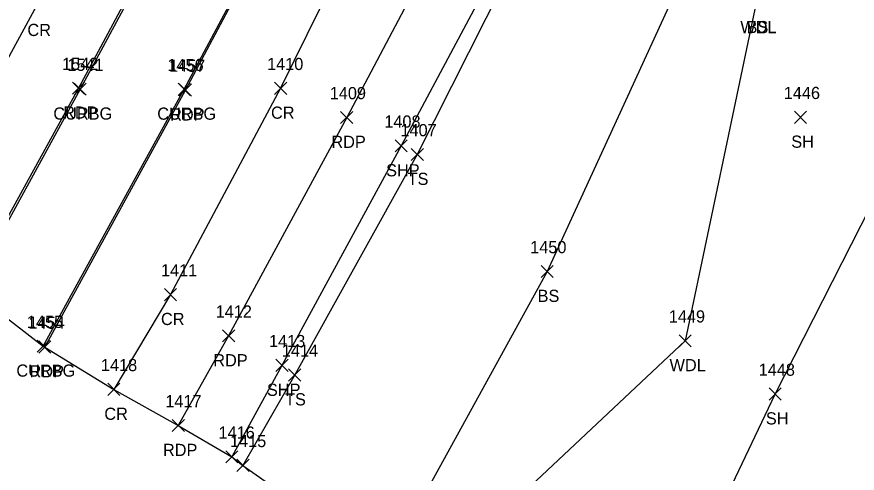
# Model space of a CAD drawing. Extents: x 1623612 to 1625808, y 621345 to 627748.
# Drawn here: x 1624455.5 to 1624593.5, y 625672.8 to 625747.8 of the extents above; entities that cross this region are included whole.
import ezdxf

# ---------------------------------------------------------------- set-up
doc = ezdxf.new("R2010")
doc.units = 0
for name, color, linetype in [('L_A', 7, 'Continuous'), ('L_I', 7, 'Continuous'), ('L_TIC', 7, 'Continuous'), ('LAWA', 7, 'Continuous'), ('LELB', 7, 'Continuous'), ('LSOGP', 7, 'Continuous'), ('P_A', 7, 'Continuous'), ('P_I', 7, 'Continuous'), ('P_TIC', 7, 'Continuous'), ('PET', 7, 'Continuous'), ('PRC', 7, 'Continuous'), ('PSP', 7, 'Continuous'), ('R_A', 7, 'Continuous'), ('R_I', 7, 'Continuous'), ('R_TIC', 7, 'Continuous'), ('RC', 7, 'Continuous')]:
    doc.layers.add(name, color=color, linetype=linetype)

msp = doc.modelspace()

# ---------------------------------------------------------------- linework, layer by layer
at = {"layer": 'L_TIC'}
for points in [[(1624583.14, 625730.27), (1624585.14, 625732.27)], [(1624585.14, 625730.27), (1624583.14, 625732.27)], [(1624520.23, 625724.16), (1624522.23, 625726.16)], [(1624522.23, 625724.16), (1624520.23, 625726.16)], [(1624541.54, 625704.94), (1624543.54, 625706.94)], [(1624543.54, 625704.94), (1624541.54, 625706.94)], [(1624564.22, 625693.56), (1624566.22, 625695.56)], [(1624566.22, 625693.56), (1624564.22, 625695.56)], [(1624500.1, 625687.94), (1624502.1, 625689.94)], [(1624502.1, 625687.94), (1624500.1, 625689.94)], [(1624578.98, 625684.81), (1624580.98, 625686.81)], [(1624580.98, 625684.81), (1624578.98, 625686.81)], [(1624491.6, 625673.09), (1624493.6, 625675.09)], [(1624493.6, 625673.09), (1624491.6, 625675.09)]]:
    msp.add_lwpolyline(points, dxfattribs=at)
at = {"layer": 'LAWA'}
msp.add_lwpolyline([(1624637.25, 625770.76), (1624576.85, 625750.09), (1624565.22, 625694.56), (1624521.74, 625653.69)], dxfattribs=at)
at = {"layer": 'LELB'}
for points in [[(1624703.97, 626118.88), (1624686.38, 626080.62), (1624681.08, 626059.17), (1624675.33, 626051.53), (1624659.81, 626015.24), (1624646.71, 625979.83), (1624626.49, 625919.66), (1624601.19, 625875.12), (1624577.24, 625833.33), (1624557.07, 625794.42), (1624540.93, 625764.23), (1624521.23, 625725.16), (1624501.1, 625688.94), (1624492.6, 625674.09)], [(1624623.85, 625843.99), (1624616.38, 625836.88), (1624604.12, 625817.6), (1624587.3, 625790.93), (1624564.35, 625753.47), (1624542.54, 625705.94), (1624515.98, 625657.65)]]:
    msp.add_lwpolyline(points, dxfattribs=at)
at = {"layer": 'LSOGP'}
for points in [[(1624410.91, 625910.13), (1624379.58, 625859.99), (1624353.03, 625816.24), (1624327.92, 625775.69), (1624362.47, 625753.11), (1624384.68, 625740.82), (1624405.5, 625728.14), (1624414.82, 625722.7), (1624417.68, 625720.8), (1624425.67, 625715.65), (1624436.82, 625709.28), (1624447.42, 625703.06), (1624447.8, 625702.94), (1624459.81, 625693.66), (1624460.07, 625693.53), (1624471.41, 625686.57), (1624481.98, 625680.63), (1624490.77, 625675.48), (1624492.6, 625674.09), (1624515.98, 625657.65)], [(1624549.56, 625621.85), (1624579.98, 625685.81), (1624598.8, 625722.78), (1624637.25, 625770.76), (1624651.69, 625796.18), (1624662.52, 625817.48), (1624670.26, 625849.95), (1624695.74, 625903.84)]]:
    msp.add_lwpolyline(points, dxfattribs=at)
at = {"layer": 'P_TIC'}
for points in [[(1624464.59, 625735.05), (1624466.59, 625737.05)], [(1624466.59, 625735.05), (1624464.59, 625737.05)], [(1624482.15, 625734.74), (1624484.15, 625736.74)], [(1624484.15, 625734.74), (1624482.15, 625736.74)], [(1624497.78, 625735.03), (1624499.78, 625737.03)], [(1624499.78, 625735.03), (1624497.78, 625737.03)], [(1624508.63, 625730.24), (1624510.63, 625732.24)], [(1624510.63, 625730.24), (1624508.63, 625732.24)], [(1624517.58, 625725.57), (1624519.58, 625727.57)], [(1624519.58, 625725.57), (1624517.58, 625727.57)], [(1624479.71, 625701.14), (1624481.71, 625703.14)], [(1624481.71, 625701.14), (1624479.71, 625703.14)], [(1624489.24, 625694.36), (1624491.24, 625696.36)], [(1624491.24, 625694.36), (1624489.24, 625696.36)], [(1624459.07, 625692.53), (1624461.07, 625694.53)], [(1624461.07, 625692.53), (1624459.07, 625694.53)], [(1624498, 625689.51), (1624500, 625691.51)], [(1624500, 625689.51), (1624498, 625691.51)], [(1624470.41, 625685.57), (1624472.41, 625687.57)], [(1624472.41, 625685.57), (1624470.41, 625687.57)], [(1624480.98, 625679.63), (1624482.98, 625681.63)], [(1624482.98, 625679.63), (1624480.98, 625681.63)], [(1624489.77, 625674.48), (1624491.77, 625676.48)], [(1624491.77, 625674.48), (1624489.77, 625676.48)]]:
    msp.add_lwpolyline(points, dxfattribs=at)
at = {"layer": 'PET'}
for points in [[(1624700.76, 626272.27), (1624689.28, 626244.04), (1624672.95, 626203.67), (1624657.22, 626165.07), (1624639.97, 626122.42), (1624626.87, 626089.89), (1624609.23, 626047.25), (1624593.09, 626008.04), (1624578.04, 625971.53), (1624565.57, 625940.71), (1624555.47, 625915.78), (1624541.27, 625885.85), (1624534.37, 625871.9), (1624518.06, 625838.28), (1624503.61, 625808.5), (1624484.54, 625771.45), (1624465.59, 625736.05), (1624447.42, 625703.06)], [(1624697.29, 626122.48), (1624678.78, 626081.29), (1624660.95, 626038.77), (1624644.98, 625998.6), (1624626.67, 625954.13), (1624613.79, 625925.45), (1624589.8, 625879.72), (1624567.17, 625838.88), (1624546.44, 625801.43), (1624529.95, 625769.7), (1624509.63, 625731.24), (1624490.24, 625695.36), (1624481.98, 625680.63)], [(1624460.07, 625693.53), (1624483.15, 625735.74), (1624499.1, 625765.66), (1624511.9, 625793.12), (1624522.35, 625825.42), (1624529.91, 625846.85), (1624536.42, 625862.69), (1624541.8, 625875.32), (1624543.5, 625883.34), (1624544.97, 625882.88), (1624547, 625887.27), (1624554.88, 625905.73), (1624572.42, 625947.53), (1624589.16, 625987.94), (1624606.66, 626030.36), (1624622.98, 626070.33), (1624637.54, 626106.17)]]:
    msp.add_lwpolyline(points, dxfattribs=at)
at = {"layer": 'PRC'}
for points in [[(1624436.82, 625709.28), (1624458.78, 625749.62), (1624477.65, 625785.2), (1624498.86, 625827.51), (1624517.91, 625866.07), (1624535.88, 625905.07), (1624552.01, 625941.13), (1624568.1, 625980.06), (1624584.2, 626018.31), (1624601.56, 626060.15), (1624617.86, 626100.59), (1624633.9, 626140.47), (1624649.73, 626177.64), (1624664.57, 626215.84), (1624677.89, 626248.35), (1624689.08, 626275.05), (1624700.91, 626304.1), (1624709.94, 626325.53), (1624717.47, 626344.65), (1624728.1, 626371.26)], [(1624756.75, 626332.96), (1624737.87, 626288.85), (1624717.83, 626237.45), (1624702.63, 626201.76), (1624690.94, 626172.24), (1624674.42, 626133.37), (1624657.37, 626090.13), (1624639.98, 626048.33), (1624623.77, 626007.33), (1624605.45, 625965.01), (1624592.56, 625934.47), (1624571.33, 625886.27), (1624551.87, 625847.8), (1624534.65, 625807.4), (1624518.3, 625775.7), (1624498.78, 625736.03), (1624480.71, 625702.14), (1624471.41, 625686.57)]]:
    msp.add_lwpolyline(points, dxfattribs=at)
at = {"layer": 'PSP'}
msp.add_lwpolyline([(1624701.4, 626121.26), (1624681.91, 626079.85), (1624663.33, 626037.3), (1624647.64, 625997), (1624629.31, 625952.35), (1624617.52, 625923.63), (1624596.53, 625876.44), (1624575.28, 625834.53), (1624555.05, 625795.64), (1624539.05, 625764.96), (1624518.58, 625726.57), (1624499, 625690.51), (1624490.77, 625675.48)], dxfattribs=at)
at = {"layer": 'R_TIC'}
for points in [[(1624464.88, 625734.89), (1624466.88, 625736.89)], [(1624466.88, 625734.89), (1624464.88, 625736.89)], [(1624481.94, 625734.87), (1624483.94, 625736.87)], [(1624483.94, 625734.87), (1624481.94, 625736.87)], [(1624458.81, 625692.66), (1624460.81, 625694.66)], [(1624460.81, 625692.66), (1624458.81, 625694.66)]]:
    msp.add_lwpolyline(points, dxfattribs=at)
at = {"layer": 'RC'}
for points in [[(1624700.99, 626272.06), (1624689.6, 626244.03), (1624673.22, 626203.62), (1624657.61, 626165.02), (1624640.13, 626122.2), (1624627.02, 626089.91), (1624609.59, 626047.26), (1624593.5, 626007.85), (1624578.4, 625971.27), (1624565.79, 625940.64), (1624555.58, 625915.85), (1624541.27, 625885.85), (1624534.86, 625871.82), (1624518.48, 625838.05), (1624503.94, 625808.16), (1624484.9, 625771.28), (1624465.88, 625735.89), (1624447.8, 625702.94)], [(1624459.81, 625693.66), (1624482.94, 625735.87), (1624498.94, 625765.8), (1624511.54, 625793.53), (1624521.86, 625825.58), (1624529.54, 625846.97), (1624536.34, 625862.92), (1624541.75, 625875.46), (1624543.5, 625883.34)]]:
    msp.add_lwpolyline(points, dxfattribs=at)

# ---------------------------------------------------------------- texts
at = {"layer": 'L_A'}
for s, p in [('WDL', (1624574.27, 625745.09)), ('BS', (1624575.29, 625745.09)), ('SH', (1624582.63, 625726.27)), ('TS', (1624519.64, 625720.16)), ('BS', (1624540.98, 625700.94)), ('WDL', (1624562.64, 625689.56)), ('TS', (1624499.51, 625683.94)), ('SH', (1624578.46, 625680.81))]:
    msp.add_text(s, height=2, dxfattribs=at).set_placement(p)
at = {"layer": 'L_I'}
for s, p in [('1446', (1624581.4, 625734.27)), ('1407', (1624518.46, 625728.16)), ('1450', (1624539.76, 625708.94)), ('1449', (1624562.52, 625697.56)), ('1414', (1624498.98, 625691.94)), ('1448', (1624577.28, 625688.81)), ('1415', (1624490.47, 625677.09))]:
    msp.add_text(s, height=2, dxfattribs=at).set_placement(p)
at = {"layer": 'P_A'}
for s, p in [('CR', (1624457.21, 625744.62)), ('RDP', (1624463.08, 625731.05)), ('RDP', (1624480.64, 625730.74)), ('CR', (1624497.21, 625731.03)), ('RDP', (1624507.12, 625726.24)), ('SHP', (1624516.11, 625721.57)), ('CR', (1624479.14, 625697.14)), ('RDP', (1624487.73, 625690.36)), ('RDP', (1624457.56, 625688.53)), ('SHP', (1624496.54, 625685.51)), ('CR', (1624469.84, 625681.57)), ('RDP', (1624479.47, 625675.63))]:
    msp.add_text(s, height=2, dxfattribs=at).set_placement(p)
at = {"layer": 'P_I'}
for s, p in [('1542', (1624462.9, 625739.05)), ('1457', (1624480.46, 625738.74)), ('1410', (1624496.56, 625739.03)), ('1409', (1624506.85, 625734.24)), ('1408', (1624515.81, 625729.57)), ('1411', (1624479.15, 625705.14)), ('1412', (1624488.12, 625698.36)), ('1454', (1624457.38, 625696.53)), ('1413', (1624496.88, 625693.51)), ('1418', (1624469.28, 625689.57)), ('1417', (1624479.85, 625683.63)), ('1416', (1624488.59, 625678.48))]:
    msp.add_text(s, height=2, dxfattribs=at).set_placement(p)
at = {"layer": 'R_A'}
for p in [(1624461.47, 625730.89), (1624478.53, 625730.87), (1624455.4, 625688.66)]:
    msp.add_text('CURBG', height=2, dxfattribs=at).set_placement(p)
at = {"layer": 'R_I'}
for s, p in [('1541', (1624463.76, 625738.89)), ('1456', (1624480.19, 625738.87)), ('1455', (1624457.12, 625696.66))]:
    msp.add_text(s, height=2, dxfattribs=at).set_placement(p)

doc.saveas('drawing.dxf')
